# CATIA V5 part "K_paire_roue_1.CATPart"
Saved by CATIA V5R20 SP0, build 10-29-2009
Part number: paire_roue_1
Publications: "Corps principal", "Plan.5"
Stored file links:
  G:\Khaled_CFAO_2011\ST2M\ST2M_GR2\echouteau\Khaled\CAD_ThinkMotion\K_paire_roue_1.CATPart
  F:\2A\Proj Think Motion\trainv3\Version3\sql_general.CATProduct
  G:\Khaled_CFAO_2011\ST2M\ST2M_GR2\echouteau\Khaled\CAD_ThinkMotion\K_bogie_beam.CATPart

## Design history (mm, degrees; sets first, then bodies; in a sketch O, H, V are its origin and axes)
Set1
  Plane1: linked copy from another document
  Point1: linked copy from another document
Body1 (main body)
  Plane2: type Offset, RefPlane Plane1, Offset 150
  Plane3: type Offset, RefPlane Plane1, Offset -150
  Point2: type OnPlane, Support Plane2, RefPoint Point1, H 0, V 0, Direction (0, -1, 0)
  Point3: type OnPlane, Support Plane3, RefPoint Point1, H 0, V 0, Direction (0, -1, 0)
  Line1: type PtPt, FirstPoint Point2, SecondPoint Point3
  Line2: type Normal, RefPoint Point3, RefSkin Plane3, Start 0, End -150
  Plane4: type OffsetPt, RefPlane Plane1, RefPoint Point3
